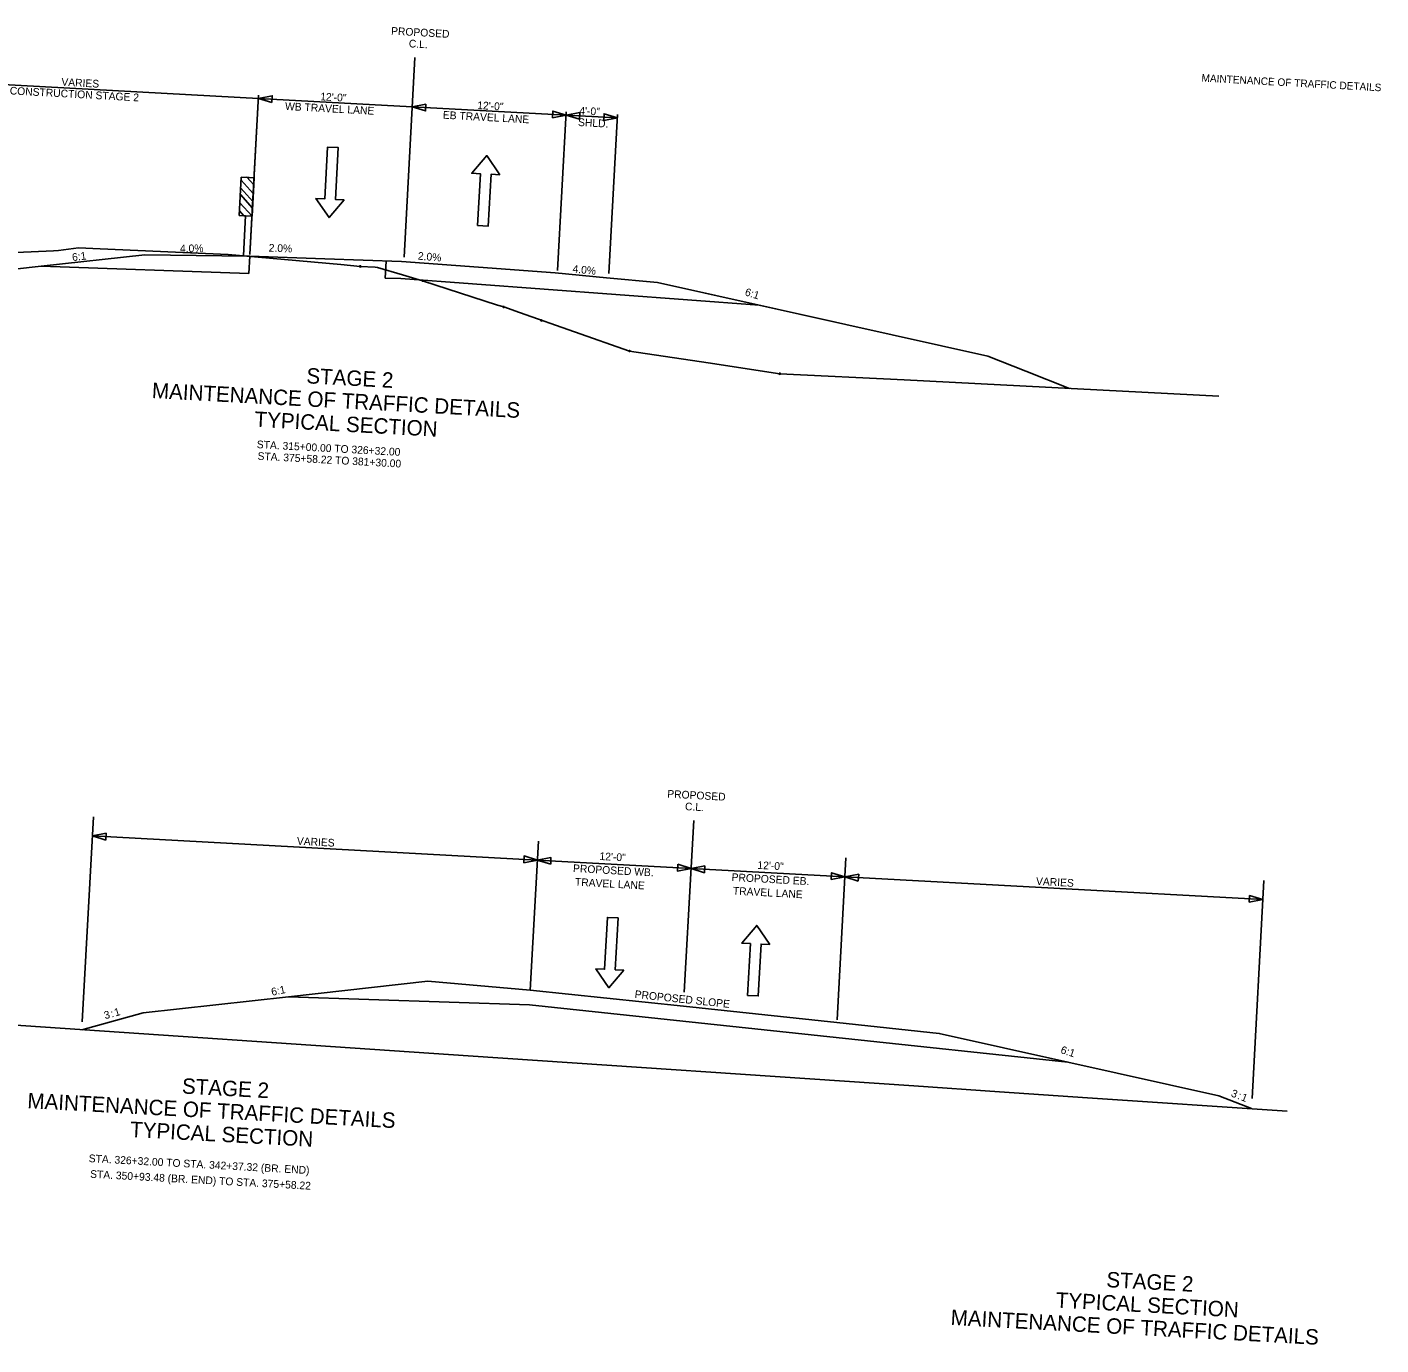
# Model space of a CAD drawing. Extents: x 879481 to 881064, y 1566477 to 1567504.
# Drawn here: x 880010 to 881064, y 1566477 to 1567504 of the extents above; entities that cross this region are included whole.
import ezdxf

# ---------------------------------------------------------------- set-up
doc = ezdxf.new("R2010")
doc.units = 0
for name, color, linetype in [('Default', 7, 'Continuous'), ('Level 1', 7, 'Continuous'), ('R_Border', 7, 'Continuous'), ('R_Border Notes', 7, 'Continuous'), ('R_Border Prem', 7, 'Continuous'), ('R_Dimension', 7, 'Continuous'), ('R_Exist Surface', 7, 'Continuous'), ('R_Fin Surface', 7, 'Continuous'), ('R_Horz Alg', 7, 'Continuous'), ('R_Sheet Text', 7, 'Continuous'), ('R_Xsect Slope', 7, 'Continuous'), ('STAMP', 7, 'Continuous'), ('STAMP_PP', 7, 'Continuous')]:
    doc.layers.add(name, color=color, linetype=linetype)

msp = doc.modelspace()

# ---------------------------------------------------------------- linework, layer by layer
at = {"layer": 'Default'}
for points in [[(880256.9, 1567369.2), (880245.1, 1567355.5), (880234.9, 1567370.4), (880241.8, 1567370), (880244, 1567410.4), (880252.2, 1567410), (880250, 1567369.6)], [(880378.1, 1567388.8), (880367.9, 1567403.7), (880356.2, 1567390), (880363, 1567389.6), (880360.8, 1567349.3), (880369.1, 1567348.8), (880371.3, 1567389.2)], [(880474.8, 1566769.2), (880463.1, 1566755.5), (880452.9, 1566770.4), (880459.7, 1566770), (880461.9, 1566810.4), (880470.2, 1566810), (880468, 1566769.6)], [(880588.4, 1566789.2), (880578.2, 1566804.1), (880566.5, 1566790.4), (880573.3, 1566790), (880571.1, 1566749.6), (880579.4, 1566749.2), (880581.6, 1566789.6)]]:
    msp.add_lwpolyline(points, close=True, dxfattribs=at)
at = {"layer": 'Defpoints'}
for p, q in [((880180.1, 1567356.8), (880178.4, 1567325.9)), ((880183.4, 1567325.3), (880182.7, 1567312)), ((880288.9, 1567308.3), (880289.6, 1567321.6)), ((880288.9, 1567308.3), (880300.9, 1567307.9)), ((880580.2, 1567287.1), (880300.9, 1567307.9)), ((880758.3, 1567247.4), (880501, 1567304.8)), ((880639.6, 1567273.9), (880501, 1567304.8))]:
    msp.add_line(p, q, dxfattribs=at)
for points in [[(880501, 1567304.8), (880461.2, 1567308.5), (880421.3, 1567312.3), (880361.5, 1567316.8), (880301.6, 1567321.2), (880241.7, 1567323.3), (880183.4, 1567325.3)], [(880758.3, 1567247.4), (880787.7, 1567235.7), (880821.7, 1567222.3)]]:
    msp.add_lwpolyline(points, dxfattribs=at)
msp.add_lwpolyline([(880640.1, 1566716.8), (880820.6, 1566697.7), (880720.4, 1566720), (880640.7, 1566728.5), (880521.2, 1566741.1), (880401.8, 1566753.8), (880322, 1566760.7), (880213.6, 1566748.6), (880401.1, 1566742.2), (880520.6, 1566729.5)], close=True, dxfattribs=at)
at = {"layer": 'Level 1'}
for p, q in [((880176.7, 1567387), (880186.7, 1567386.5)), ((880186.7, 1567386.5), (880176.7, 1567387)), ((880176.7, 1567387), (880183, 1567386.7)), ((880176.7, 1567384.6), (880186.1, 1567374.1)), ((880186.4, 1567380.9), (880181.1, 1567386.8)), ((880186.7, 1567386.9), (880185.1, 1567357)), ((880186.7, 1567386.5), (880185.1, 1567356.5)), ((880176, 1567373.3), (880185.4, 1567362.8)), ((880185.7, 1567367.9), (880176.3, 1567378.4)), ((880185.1, 1567357), (880186.4, 1567381.4)), ((880185.1, 1567356.5), (880186.4, 1567380.9)), ((880186.1, 1567374.1), (880185.7, 1567367.9)), ((880185.1, 1567356.5), (880175.6, 1567367)), ((880185.1, 1567356.5), (880175.7, 1567367)), ((880175.7, 1567367), (880185.1, 1567356.5)), ((880175.1, 1567357.1), (880185.1, 1567356.5)), ((880178.7, 1567356.9), (880175.3, 1567360.7)), ((880185.1, 1567356.5), (880178.7, 1567356.9))]:
    msp.add_line(p, q, dxfattribs=at)
msp.add_lwpolyline([(880183, 1567386.7), (880181.1, 1567386.8), (880183.8, 1567383.8), (880186.4, 1567380.9), (880186.5, 1567382.8)], dxfattribs=at)
at = {"layer": 'R_Border'}
for q in [(880101.6, 1567326.5), (880182.7, 1567312)]:
    msp.add_line((880021, 1567317.5), q, dxfattribs=at)
msp.add_lwpolyline([(880183.4, 1567325.3), (880181.7, 1567325.3), (880141.7, 1567325.9), (880101.6, 1567326.5)], dxfattribs=at)
at = {"layer": 'R_Border Notes'}
msp.add_lwpolyline([(880176.7, 1567387), (880175.1, 1567357.1), (880185.1, 1567356.5)], dxfattribs=at)
at = {"layer": 'R_Dimension'}
for p, q in [((880190.1, 1567448.3), (879901.7, 1567463.9)), ((880183.7, 1567331.1), (880190.2, 1567450.9)), ((880190.1, 1567448.3), (880309.9, 1567441.7)), ((880429.7, 1567435.2), (880309.9, 1567441.7)), ((880423.1, 1567314.1), (880429.9, 1567437.9)), ((880463.1, 1567311.9), (880469.8, 1567435.7)), ((880469.7, 1567433), (880429.7, 1567435.2)), ((880052.9, 1566729), (880061.6, 1566888.6)), ((880407.3, 1566855), (880060.8, 1566873.8)), ((880401.8, 1566753.8), (880408.1, 1566869.8)), ((880640.8, 1566730.5), (880647.7, 1566856.8)), ((880407.3, 1566855), (880527.1, 1566848.4)), ((880646.9, 1566841.9), (880527.1, 1566848.4)), ((880972.4, 1566824.2), (880646.9, 1566841.9)), ((880964, 1566669.2), (880973.2, 1566839))]:
    msp.add_line(p, q, dxfattribs=at)
msp.add_lwpolyline([(880183.5, 1567326.6), (880185, 1567355.8), (880190.2, 1567450.9)], dxfattribs=at)
for points in [[(880200.5, 1567445), (880190.1, 1567448.3), (880200.8, 1567450.3)], [(880320.6, 1567443.8), (880309.9, 1567441.7), (880320.3, 1567438.5)], [(880419, 1567433.2), (880429.7, 1567435.2), (880419.3, 1567438.4)], [(880440.1, 1567432), (880429.7, 1567435.2), (880440.4, 1567437.3)], [(880459, 1567431), (880469.7, 1567433), (880459.3, 1567436.3)], [(880071.2, 1566870.6), (880060.8, 1566873.8), (880071.5, 1566875.9)], [(880396.7, 1566852.9), (880407.4, 1566855), (880397, 1566858.2)], [(880417.7, 1566851.8), (880407.3, 1566855), (880417.9, 1566857)], [(880516.7, 1566851.7), (880527.1, 1566848.4), (880516.4, 1566846.4)], [(880537.8, 1566850.5), (880527.1, 1566848.4), (880537.5, 1566845.2)], [(880636.2, 1566839.9), (880646.9, 1566841.9), (880636.5, 1566845.1)], [(880657.3, 1566838.7), (880646.9, 1566841.9), (880657.6, 1566844)], [(880961.7, 1566822.2), (880972.4, 1566824.2), (880962, 1566827.4)]]:
    msp.add_lwpolyline(points, close=True, dxfattribs=at)
at = {"layer": 'R_Exist Surface'}
for points in [[(879642.6, 1567281.3), (879793.7, 1567277.2), (879894.5, 1567303.6), (879902.2, 1567305.7), (879908.1, 1567307.2), (879983.7, 1567327.6), (880001.3, 1567328.3), (880030.6, 1567329.5), (880034.4, 1567329.8), (880049.9, 1567331.8), (880066.7, 1567331.1)], [(880066.7, 1567331.1), (880166.6, 1567326.8), (880254.2, 1567318.8), (880269.4, 1567317.4), (880281.1, 1567316.7), (880282.7, 1567316.6), (880302.3, 1567310.9), (880318, 1567306.3), (880376.3, 1567287.3), (880381.1, 1567285.8), (880393.4, 1567281.4), (880479.1, 1567251.5), (880540.3, 1567242.4), (880596.1, 1567233.8), (880693.1, 1567229), (880938.1, 1567216.3)], [(879978.1, 1566728), (880353.5, 1566702.5), (880700.6, 1566679.1), (880767.2, 1566674.5), (880835.8, 1566669.9), (880991.4, 1566659.5)]]:
    msp.add_lwpolyline(points, dxfattribs=at)
at = {"layer": 'R_Fin Surface'}
for points in [[(880213.6, 1566748.6), (880100.3, 1566736)], [(880820.6, 1566697.7), (880938.1, 1566671.5)]]:
    msp.add_lwpolyline(points, dxfattribs=at)
at = {"layer": 'R_Horz Alg'}
for p, q in [((880303.5, 1567324.6), (880312, 1567480.2)), ((880527.1, 1566849.3), (880529.1, 1566885.9)), ((880521.8, 1566752), (880527.1, 1566849.3))]:
    msp.add_line(p, q, dxfattribs=at)
at = {"layer": 'R_Sheet Text'}
for points in [[(880501, 1567304.8), (880461.2, 1567308.5), (880421.3, 1567312.3), (880361.5, 1567316.8), (880301.6, 1567321.2), (880241.7, 1567323.3), (880183.4, 1567325.3)], [(880021, 1567317.5), (879960.6, 1567310.8), (879893, 1567303.3)], [(880052.6, 1566722.9), (880100.3, 1566736), (880213.6, 1566748.6), (880322, 1566760.7), (880401.8, 1566753.8), (880521.2, 1566741.1), (880640.7, 1566728.5), (880720.4, 1566720), (880820.6, 1566697.7), (880938.1, 1566671.5), (880963.6, 1566661.4)]]:
    msp.add_lwpolyline(points, dxfattribs=at)
at = {"layer": 'STAMP'}
for points in [[(880100.3, 1566736), (880052.6, 1566722.9)], [(880938.1, 1566671.5), (880963.6, 1566661.4)]]:
    msp.add_lwpolyline(points, dxfattribs=at)
at = {"layer": 'STAMP_PP'}
for centre in [(880269.4, 1567317.4), (880318, 1567306.3), (880381.1, 1567285.8), (880410.4, 1567275.3), (880479.1, 1567251.5), (880596.1, 1567233.8)]:
    msp.add_circle(centre, 0.5, dxfattribs=at)

# ---------------------------------------------------------------- texts
at = {"layer": 'R_Border'}
for s, height, p in [('PROPOSED', 6, (880293.3, 1567497.9)), ('C.L.', 6, (880307.1, 1567488.1)), ('CONSTRUCTION STAGE 2', 6, (879996.3, 1567451.4)), ('VARIES', 6, (880036.5, 1567458.2)), ('12\'-0"', 6, (880238.1, 1567446.8)), ('WB TRAVEL LANE', 6, (880210.7, 1567439.3)), ('EB TRAVEL LANE', 6, (880333.6, 1567432.5)), ('12\'-0"', 6, (880360.4, 1567440)), ('4\'-0" ', 6, (880439.9, 1567435.8)), ('SHLD.', 6, (880438.9, 1567426.8)), ('STAGE 2', 12, (880227.2, 1567226.4)), ('MAINTENANCE OF TRAFFIC DETAILS', 12, (880106.9, 1567214.9)), ('TYPICAL SECTION ', 12, (880186.8, 1567192.5)), ('STA. 315+00.00 TO 326+32.00', 6, (880188.7, 1567175.9)), ('STA. 375+58.22 TO 381+30.00', 6, (880189.3, 1567166.8)), ('PROPOSED', 6, (880508.4, 1566903.7)), ('C.L.', 6, (880522.2, 1566893.9)), ('VARIES', 6, (880219.9, 1566867)), ('12\'-0"', 6, (880455.6, 1566855.1)), ('PROPOSED WB.', 6, (880435, 1566845.7)), ('12\'-0"', 6, (880578.6, 1566848.2)), ('TRAVEL LANE', 6, (880436.5, 1566835.1)), ('PROPOSED EB.', 6, (880558.5, 1566838.8)), ('VARIES', 6, (880795.6, 1566835.7)), ('TRAVEL LANE', 6, (880559.5, 1566828.2)), ('STAGE 2', 12, (880130.3, 1566673.2)), ('MAINTENANCE OF TRAFFIC DETAILS', 12, (880009.9, 1566661.8)), ('TYPICAL SECTION ', 12, (880089.9, 1566639.4)), ('STA. 326+32.00 TO STA. 342+37.32 (BR. END)', 6, (880057.8, 1566619.8)), ('STA. 350+93.48 (BR. END) TO STA. 375+58.22', 6, (880058.9, 1566607.6)), ('STAGE 2 ', 12, (880850.3, 1566522.4)), ('TYPICAL SECTION', 12, (880810.8, 1566506.5)), ('MAINTENANCE OF TRAFFIC DETAILS', 12, (880729, 1566493))]:
    msp.add_text(s, height=height, rotation=356.8871, dxfattribs=at).set_placement(p)
at = {"layer": 'R_Border Prem'}
msp.add_text('MAINTENANCE OF TRAFFIC DETAILS', height=5.862, rotation=356.8871, dxfattribs=at).set_placement((880924.5, 1567461.4))
at = {"layer": 'R_Xsect Slope'}
for s, rotation, p in [('4.0%', 0.4316, (880129, 1567328.4)), ('2.0%', 357.6303, (880198, 1567329)), ('6:1', 6.9756, (880045.3, 1567321.5)), ('2.0%', 355.3388, (880314.1, 1567322.7)), ('4.0%', 354.1939, (880434.5, 1567312.7)), ('6:1', 342.4483, (880568.5, 1567295)), ('6:1', 11.3259, (880200.7, 1566749.3)), ('PROPOSED SLOPE', 353.944, (880482.9, 1566747.7)), ('1', 15.322, (880078.7, 1566733.2)), ('3', 15.322, (880070.7, 1566731)), (':', 15.322, (880075.9, 1566732.4)), ('6:1', 342.4483, (880814.4, 1566704.7)), ('3', 338.4522, (880947.1, 1566671.1)), (':', 338.4522, (880952.1, 1566669.1)), ('1', 338.4522, (880954.9, 1566668.1))]:
    msp.add_text(s, height=6, rotation=rotation, dxfattribs=at).set_placement(p)

doc.saveas('drawing.dxf')
